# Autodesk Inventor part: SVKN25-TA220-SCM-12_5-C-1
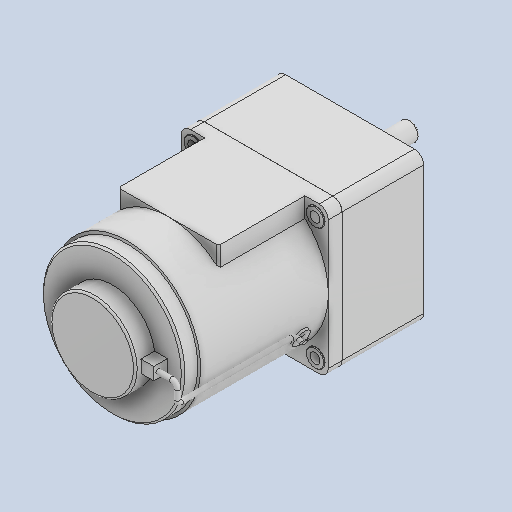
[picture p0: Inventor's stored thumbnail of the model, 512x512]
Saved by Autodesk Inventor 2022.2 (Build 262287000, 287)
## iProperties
Created: 2024-10
Part Number: SVKN25-TA220-SCM-12_5-C-1
Material: Generico
Document SubType Name: Modeling
Designer: 18907419
Density: 1 g/cm^3
Appearance: Default
Author: 18907419
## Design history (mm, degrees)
feature "Solido1"
node "Solido2"
